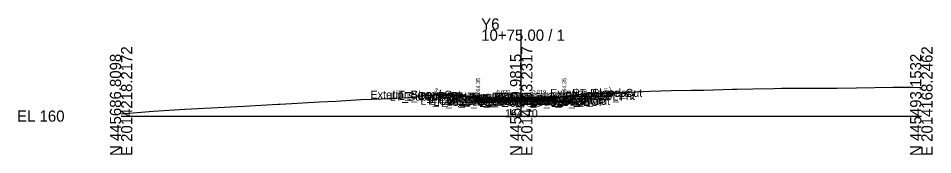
# Model space of a CAD drawing. Extents: x -26 to 203, y -10 to 4529.
# Drawn here: x -25.7 to 202.8, y 1490.3 to 1524.5 of the extents above; entities that cross this region are included whole.
import ezdxf

# ---------------------------------------------------------------- set-up
doc = ezdxf.new("R2010")
doc.units = 0
for name, color, linetype in [('Default', 7, 'Continuous'), ('Exist Cross Section Cell', 7, 'Continuous'), ('Exist XS Center Line Elevation Label', 7, 'Continuous'), ('Exist XS Ground Line', 7, 'Continuous'), ('Prop CMT Conc Surface', 7, 'Continuous'), ('Prop CMT Concrete Structures', 7, 'Continuous'), ('Prop CMT Pvmt Course 1', 7, 'Continuous'), ('Prop CMT Pvmt Course 1 CG', 7, 'Continuous'), ('Prop CMT Pvmt Course 2', 7, 'Continuous'), ('Prop CMT Pvmt Course 3', 7, 'Continuous'), ('Prop CMT Pvmt Surface', 7, 'Continuous'), ('Prop CMT Slope Grass', 7, 'Continuous'), ('Prop CMT Subgrade Earthwork', 7, 'Continuous'), ('Prop XS Earthwork Shape', 7, 'Continuous'), ('Prop XS Hydro Elevations', 7, 'Continuous'), ('Prop XS SE Text', 7, 'Continuous'), ('Prop XS Side Slope Text', 7, 'Continuous'), ('Scratch_Level_0', 7, 'Continuous')]:
    doc.layers.add(name, color=color, linetype=linetype)

msp = doc.modelspace()

# ---------------------------------------------------------------- linework, layer by layer
at = {"layer": 'Exist Cross Section Cell'}
for p, q in [((100, 1500), (100, 1521.68)), ((0, 1500), (100, 1500)), ((100, 1500), (200, 1500))]:
    msp.add_line(p, q, dxfattribs=at)
at = {"layer": 'Exist XS Ground Line'}
msp.add_lwpolyline([(0, 1500.59), (8.02, 1501.25), (15.97, 1501.7), (25.8, 1502.25), (28.9, 1502.4), (30.72, 1502.51), (37.8, 1502.89), (39.22, 1502.96), (39.72, 1502.99), (49.55, 1503.56), (53.64, 1503.71), (59.88, 1504.14), (67.56, 1504.42), (70.21, 1504.58), (71.77, 1504.65), (77.82, 1505.34), (79.98, 1505.6), (80.83, 1505.58), (91.62, 1504.44), (96.5, 1504.57), (100, 1504.7), (101.32, 1504.75), (105.72, 1504.71), (108.98, 1504.73), (114.04, 1505.32), (116.39, 1505.55), (123.87, 1505.85), (132.18, 1506.25), (137.45, 1506.39), (142.51, 1506.5), (145.66, 1506.53), (152.84, 1506.71), (153.87, 1506.74), (157.88, 1506.82), (163.17, 1506.95), (165.01, 1506.96), (173.5, 1506.99), (178.93, 1507.02), (183.83, 1507.07), (192.85, 1507.22), (194.16, 1507.23), (197.91, 1507.21), (200, 1507.19)], dxfattribs=at)
at = {"layer": 'Prop CMT Conc Surface'}
for points in [[(89.23, 1504.35), (89.22, 1504.85), (88.72, 1504.85)], [(91.23, 1504.47), (89.23, 1504.35)], [(108.76, 1504.47), (110.76, 1504.35)], [(110.76, 1504.35), (110.76, 1504.85), (111.26, 1504.85)]]:
    msp.add_lwpolyline(points, dxfattribs=at)
at = {"layer": 'Prop CMT Concrete Structures'}
for points in [[(91.23, 1504.47), (89.23, 1504.35), (89.22, 1504.85), (88.72, 1504.85)], [(88.72, 1504.85), (88.73, 1503.83), (91.23, 1503.88)], [(91.23, 1503.88), (91.23, 1504.47)], [(108.76, 1504.47), (110.76, 1504.35), (110.76, 1504.85), (111.26, 1504.85)], [(111.26, 1504.85), (111.26, 1503.84), (108.76, 1503.89)], [(108.76, 1503.89), (108.76, 1504.47)]]:
    msp.add_lwpolyline(points, dxfattribs=at)
at = {"layer": 'Prop CMT Pvmt Course 1'}
for points in [[(100, 1504.64), (91.23, 1504.47)], [(91.23, 1504.47), (91.23, 1504.22)], [(91.23, 1504.22), (100, 1504.39)], [(100, 1504.39), (100, 1504.64)], [(100, 1504.64), (108.76, 1504.47)], [(100, 1504.39), (100, 1504.64)], [(108.76, 1504.22), (100, 1504.39)], [(108.76, 1504.47), (108.76, 1504.22)]]:
    msp.add_lwpolyline(points, dxfattribs=at)
msp.add_lwpolyline([(100, 1504.39), (100, 1504.52), (100, 1504.52), (100, 1504.39)], close=True, dxfattribs=at)
msp.add_lwpolyline([(100, 1504.39), (100, 1504.52), (100, 1504.52), (100, 1504.39)], close=True, dxfattribs=at)
at = {"layer": 'Prop CMT Pvmt Course 1 CG'}
for points in [[(91.23, 1503.88), (88.23, 1503.82), (87.93, 1503.53)], [(91.23, 1503.59), (91.23, 1503.88)], [(108.76, 1503.89), (111.76, 1503.83), (112.05, 1503.53)], [(108.76, 1503.6), (108.76, 1503.89)], [(87.93, 1503.53), (91.23, 1503.59)], [(112.05, 1503.53), (108.76, 1503.6)]]:
    msp.add_lwpolyline(points, dxfattribs=at)
at = {"layer": 'Prop CMT Pvmt Course 2'}
for points in [[(100, 1504.39), (91.23, 1504.22)], [(91.23, 1504.22), (91.23, 1503.97)], [(91.23, 1503.97), (100, 1504.14)], [(100, 1504.14), (100, 1504.39)], [(100, 1504.14), (100, 1504.39)], [(100, 1504.39), (108.76, 1504.22)], [(108.76, 1503.97), (100, 1504.14)], [(108.76, 1504.22), (108.76, 1503.97)]]:
    msp.add_lwpolyline(points, dxfattribs=at)
at = {"layer": 'Prop CMT Pvmt Course 3'}
for points in [[(100, 1504.14), (91.23, 1503.97)], [(91.23, 1503.97), (91.23, 1503.59)], [(91.23, 1503.59), (100, 1503.77)], [(100, 1503.77), (100, 1504.14)], [(100, 1504.14), (108.76, 1503.97)], [(100, 1503.77), (100, 1504.14)], [(108.76, 1503.6), (100, 1503.77)], [(108.76, 1503.97), (108.76, 1503.6)]]:
    msp.add_lwpolyline(points, dxfattribs=at)
at = {"layer": 'Prop CMT Pvmt Surface'}
for points in [[(100, 1504.64), (91.23, 1504.47)], [(100, 1504.64), (108.76, 1504.47)]]:
    msp.add_lwpolyline(points, dxfattribs=at)
at = {"layer": 'Prop CMT Slope Grass'}
for points in [[(88.72, 1504.85), (79.22, 1505.04), (78.17, 1505.39)], [(111.26, 1504.85), (120.76, 1505.04), (123.07, 1505.82)]]:
    msp.add_lwpolyline(points, dxfattribs=at)
at = {"layer": 'Prop CMT Subgrade Earthwork'}
for points in [[(91.23, 1503.59), (87.93, 1503.53), (86.56, 1504.89)], [(100, 1503.77), (91.23, 1503.59)], [(100, 1503.77), (108.76, 1503.6)], [(108.76, 1503.6), (112.05, 1503.53), (113.42, 1504.9)]]:
    msp.add_lwpolyline(points, dxfattribs=at)
at = {"layer": 'Prop XS Earthwork Shape'}
for points in [[(79.22, 1505.04), (78.17, 1505.39), (79.98, 1505.6), (80.83, 1505.58), (87.52, 1504.87), (86.56, 1504.89)], [(111.26, 1503.84), (108.76, 1503.89), (108.76, 1504.47), (100, 1504.64), (96.7, 1504.58), (96.5, 1504.57), (91.62, 1504.44), (91.32, 1504.47), (91.23, 1504.47), (91.23, 1503.88), (88.73, 1503.83), (88.73, 1504.74), (87.52, 1504.87), (86.56, 1504.89), (87.93, 1503.53), (91.23, 1503.59), (100, 1503.77), (108.76, 1503.6), (112.05, 1503.53), (113.42, 1504.9), (111.26, 1504.85)], [(91.23, 1504.47), (89.23, 1504.35), (89.23, 1504.69), (88.73, 1504.74), (88.73, 1503.83), (91.23, 1503.88)], [(89.23, 1504.69), (91.32, 1504.47), (91.23, 1504.47), (89.23, 1504.35)], [(120.76, 1505.04), (123.07, 1505.82), (116.39, 1505.55), (114.04, 1505.32), (108.98, 1504.73), (105.72, 1504.71), (101.32, 1504.75), (100, 1504.7), (96.7, 1504.58), (100, 1504.64), (108.76, 1504.47), (110.76, 1504.35), (110.76, 1504.85), (111.26, 1504.85), (113.42, 1504.9)], [(111.26, 1503.84), (108.76, 1503.89), (108.76, 1504.47), (110.76, 1504.35), (110.76, 1504.85), (111.26, 1504.85)]]:
    msp.add_lwpolyline(points, close=True, dxfattribs=at)

# ---------------------------------------------------------------- texts
at = {"layer": 'Default'}
msp.add_text('-', height=0.0001, dxfattribs=at).set_placement((0, 1500))
at = {"layer": 'Exist Cross Section Cell'}
for s, p in [('Y6', (90, 1521.68)), ('10+75.00 / 1', (90, 1518.88)), ('EL 160', (-26, 1498.6))]:
    msp.add_text(s, height=2.8, dxfattribs=at).set_placement(p)
for s, p in [('N 445686.8098', (0, 1490)), ('E 2014218.2172', (2.8, 1490)), ('N 445589.9815', (100, 1490)), ('E 2014193.2317', (102.8, 1490)), ('N 445493.1532', (200, 1490)), ('E 2014168.2462', (202.8, 1490))]:
    msp.add_text(s, height=2.8, rotation=90, dxfattribs=at).set_placement(p)
at = {"layer": 'Exist XS Center Line Elevation Label'}
msp.add_text('164.70', height=2, dxfattribs=at).set_placement((95.95, 1499.7))
at = {"layer": 'Prop XS Hydro Elevations'}
for p in [(89.73, 1505.35), (111.26, 1505.35)]:
    msp.add_text('164.35', height=1, rotation=90, dxfattribs=at).set_placement(p)
at = {"layer": 'Prop XS SE Text'}
for s, rotation, p in [('0.020', 1.1458, (93.84, 1505.52)), ('0.019', 358.8879, (102.78, 1505.59))]:
    msp.add_text(s, height=1, rotation=rotation, dxfattribs=at).set_placement(p)
at = {"layer": 'Prop XS Side Slope Text'}
for rotation, p in [(341.5652, (78.2, 1506.17)), (18.4332, (120.94, 1505.89))]:
    msp.add_text('3:1', height=1, rotation=rotation, dxfattribs=at).set_placement(p)
at = {"layer": 'Scratch_Level_0'}
for s, p in [('Exterior Boundary', (62.35, 1504.38)), ('LT_Slope_Cut', (67.84, 1504.38)), ('LT_CSLP_Pnt', (69.4, 1504.04)), ('Exterior Boundary', (107.24, 1504.82)), ('RT_CSLP_Pnt', (110.88, 1504.04)), ('RT_Slope_Cut', (112.69, 1504.82)), ('LT_Sub_Trench_Out_DLT', (67.13, 1503.89)), ('LT_CG1_Shelf_Out', (74.78, 1502.82)), ('LT_CG_Top_Face', (76.48, 1503.85)), ('LT_CG_Top_BOC', (77.01, 1503.85)), ('LT_CG_Bot_BOC', (77.04, 1502.83)), ('LT_CG_Top_Gut', (77.46, 1503.35)), ('LT_Sub_OEOP', (78.04, 1502.53)), ('LT_CG_Bot_IE', (81.14, 1502.88)), ('LT_Sub_OEOT', (81.3, 1502.59)), ('LT_PV2_OEOT', (81.4, 1503.22)), ('LT_PV3_OEOT', (81.4, 1502.97)), ('LT_PV1_OEOT', (81.97, 1503.47)), ('RT_Sub_OEEOP', (89.17, 1502.77)), ('LT_Sub_OEEOP', (89.21, 1502.77)), ('RT_PV2_OEEOP', (89.26, 1503.39)), ('RT_PV3_OEEOP', (89.26, 1503.14)), ('LT_PV2_OEEOP', (89.31, 1503.39)), ('LT_PV3_OEEOP', (89.31, 1503.14)), ('RT_PV1_OEEOP', (89.83, 1503.52)), ('LT_PV1_OEEOP', (89.87, 1503.52)), ('RT_PV2_IEEOP', (89.91, 1503.39)), ('LT_PV2_IEEOP', (89.95, 1503.39)), ('RT_PV1_IEEOP', (90.47, 1503.52)), ('LT_PV1_IEEOP', (90.52, 1503.52)), ('PV2_PGL', (93.91, 1503.39)), ('RT_Sub_Trench_Out_DLT', (93.94, 1503.9)), ('PV1_PGL', (94.47, 1503.64)), ('RT_CG_Top_Face', (97.97, 1503.85)), ('RT_CG1_Shelf_Out', (98.26, 1502.83)), ('RT_CG_Bot_IE', (98.62, 1502.89)), ('RT_Sub_OEOT', (98.79, 1502.6)), ('RT_PV2_OEOT', (98.88, 1503.22)), ('RT_PV3_OEOT', (98.88, 1502.97)), ('RT_CG_Top_Gut', (98.94, 1503.35)), ('RT_PV1_OEOT', (99.45, 1503.47)), ('RT_CG_Top_BOC', (99.49, 1503.85)), ('RT_CG_Bot_BOC', (99.52, 1502.84)), ('RT_Sub_OEOP', (102.12, 1502.53))]:
    msp.add_text(s, height=2, dxfattribs=at).set_placement(p)

doc.saveas('drawing.dxf')
